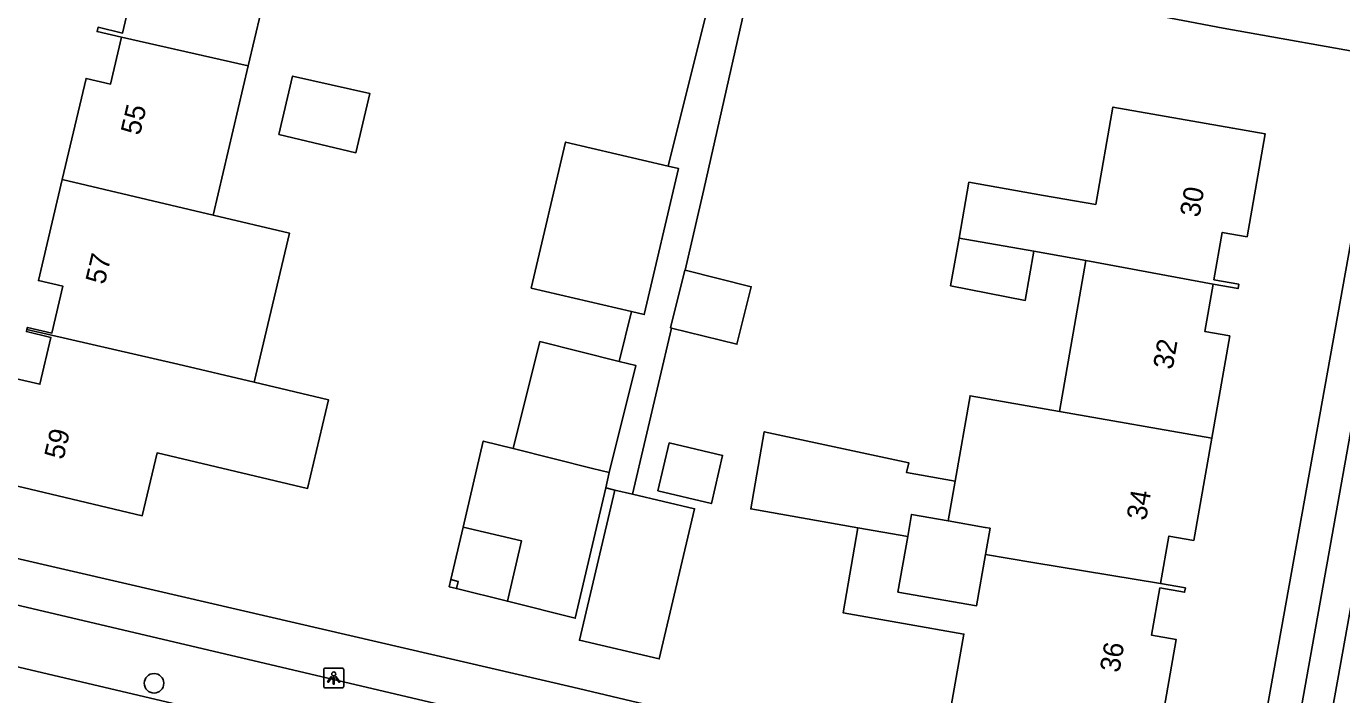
# Model space of a CAD drawing. Extents: x 163686 to 164493, y 382719 to 383870.
# Drawn here: x 163838.9 to 163904.7, y 383427.9 to 383461.3 of the extents above; entities that cross this region are included whole.
import ezdxf

# ---------------------------------------------------------------- set-up
doc = ezdxf.new("R2010")
doc.units = 0
for name, color, linetype in [('IMGEO_Boom', 7, 'Continuous'), ('IMGEO_Groenvoorziening', 7, 'Continuous'), ('IMGEO_Lichtpunt', 7, 'Continuous'), ('IMGEO_Muur', 7, 'Continuous'), ('IMGEO_Pand', 7, 'Continuous'), ('IMGEO_Pand_nummerreeks', 7, 'Continuous'), ('IMGEO_Pand_overbouw', 7, 'Continuous'), ('IMGEO_Rijbaan_lokaal_open', 7, 'Continuous'), ('IMGEO_Voetpad_open', 7, 'Continuous')]:
    doc.layers.add(name, color=color, linetype=linetype)

msp = doc.modelspace()

# ---------------------------------------------------------------- linework, layer by layer
at = {"layer": 'IMGEO_Boom'}
msp.add_circle((163845.296, 383428.434), 0.489, dxfattribs=at)
at = {"layer": 'IMGEO_Groenvoorziening'}
msp.add_lwpolyline([(163861.569, 383423.819), (163837.373, 383429.512)], dxfattribs=at)
at = {"layer": 'IMGEO_Lichtpunt'}
for p, q in [((163853.789, 383429.101), (163853.789, 383428.294)), ((163853.789, 383429.101), (163853.789, 383428.294)), ((163854.691, 383429.196), (163853.883, 383429.196)), ((163854.691, 383429.196), (163853.883, 383429.196)), ((163854.785, 383428.294), (163854.785, 383429.101)), ((163854.785, 383428.294), (163854.785, 383429.101)), ((163853.883, 383428.2), (163854.691, 383428.2)), ((163853.883, 383428.2), (163854.691, 383428.2))]:
    msp.add_line(p, q, dxfattribs=at)
for points in [[(163854.163, 383428.765), (163854.202, 383428.737), (163854.014, 383428.475), (163853.976, 383428.502), (163854.163, 383428.765)], [(163854.265, 383428.717), (163854.312, 383428.717), (163854.312, 383428.395), (163854.265, 383428.395), (163854.265, 383428.717)], [(163854.375, 383428.737), (163854.413, 383428.764), (163854.6, 383428.502), (163854.561, 383428.474), (163854.375, 383428.737)]]:
    msp.add_lwpolyline(points, dxfattribs=at)
msp.add_circle((163854.288, 383428.899), 0.0994, dxfattribs=at)
for centre, start, end in [((163853.883, 383429.101), 90, 180), ((163853.883, 383429.101), 90, 180), ((163854.691, 383429.101), 0, 90), ((163854.691, 383429.101), 0, 90), ((163853.883, 383428.294), 180, 270), ((163853.883, 383428.294), 180, 270), ((163854.691, 383428.294), 270, 0), ((163854.691, 383428.294), 270, 360)]:
    msp.add_arc(centre, 0.0946, start, end, dxfattribs=at)
at = {"layer": 'IMGEO_Muur'}
for points in [[(163837.936, 383434.797), (163843.936, 383433.408)], [(163843.936, 383433.408), (163866.249, 383428.241)]]:
    msp.add_lwpolyline(points, dxfattribs=at)
at = {"layer": 'IMGEO_Pand'}
for points in [[(163843.673, 383460.79), (163842.444, 383461.07), (163842.494, 383461.284), (163843.721, 383460.996), (163844.274, 383463.342), (163843.047, 383463.63), (163844.242, 383468.706), (163844.827, 383468.569), (163851.79, 383466.938), (163850.633, 383462.021), (163850.004, 383459.348)], [(163840.698, 383453.655), (163841.892, 383458.724), (163843.118, 383458.436), (163843.673, 383460.79)], [(163850.004, 383459.348), (163843.673, 383460.79)], [(163850.004, 383459.348), (163848.246, 383451.878)], [(163851.535, 383455.906), (163852.225, 383458.842), (163856.096, 383457.96), (163855.4, 383454.996), (163851.535, 383455.906)], [(163885.579, 383450.722), (163886.071, 383453.525), (163889.815, 383452.867), (163892.422, 383452.409), (163893.278, 383457.284), (163893.95, 383457.166), (163899.278, 383456.23), (163900.903, 383455.945), (163899.998, 383450.792), (163898.757, 383451.01), (163898.34, 383448.636), (163899.581, 383448.418), (163899.543, 383448.201), (163898.302, 383448.419)], [(163871.016, 383454.334), (163865.887, 383455.534), (163864.176, 383448.22), (163869.197, 383447.045)], [(163869.197, 383447.045), (163869.825, 383446.898), (163871.536, 383454.212), (163871.016, 383454.334)], [(163838.93, 383446.148), (163838.955, 383446.255), (163840.182, 383445.967), (163840.735, 383448.313), (163839.506, 383448.601), (163840.698, 383453.655)], [(163848.246, 383451.878), (163840.698, 383453.655)], [(163848.246, 383451.878), (163852.066, 383450.979), (163850.307, 383443.507)], [(163889.322, 383450.064), (163888.89, 383447.604), (163885.161, 383448.343), (163885.579, 383450.722)], [(163885.579, 383450.722), (163889.322, 383450.064)], [(163891.93, 383449.606), (163889.322, 383450.064)], [(163890.603, 383442.047), (163891.93, 383449.606)], [(163898.302, 383448.419), (163891.93, 383449.606)], [(163871.189, 383446.223), (163871.142, 383446.235), (163871.862, 383449.12), (163871.868, 383449.118)], [(163871.189, 383446.223), (163874.461, 383445.407), (163875.181, 383448.291), (163871.868, 383449.118)], [(163898.302, 383448.419), (163897.886, 383446.046), (163899.126, 383445.828), (163898.227, 383440.708)], [(163850.307, 383443.507), (163854.021, 383442.632), (163852.977, 383438.193), (163845.445, 383439.968), (163844.705, 383436.825), (163838.738, 383438.231), (163837.153, 383438.604), (163837.497, 383440.064), (163837.063, 383440.536), (163837.497, 383442.376), (163838.095, 383442.605), (163838.352, 383443.695), (163839.579, 383443.407), (163840.132, 383445.753), (163838.904, 383446.041), (163838.93, 383446.148)], [(163850.307, 383443.507), (163846.489, 383444.407), (163838.93, 383446.148)], [(163868.575, 383444.552), (163864.608, 383445.542), (163863.271, 383440.185)], [(163868.077, 383438.986), (163869.414, 383444.342), (163868.575, 383444.552)], [(163885.38, 383438.557), (163886.131, 383442.832), (163890.603, 383442.047)], [(163890.603, 383442.047), (163898.227, 383440.708)], [(163880.522, 383436.219), (163875.153, 383437.162), (163875.832, 383441.026), (163883.065, 383439.476), (163882.959, 383438.982), (163885.38, 383438.557)], [(163863.271, 383440.185), (163861.77, 383440.56), (163860.763, 383436.246), (163863.685, 383435.564), (163862.979, 383432.538), (163866.374, 383431.691), (163867.897, 383438.216)], [(163870.51, 383438.062), (163873.186, 383437.435), (163873.75, 383439.841), (163871.074, 383440.469), (163870.51, 383438.062)], [(163898.227, 383440.708), (163897.327, 383435.584), (163896.087, 383435.802), (163895.67, 383433.428)], [(163863.271, 383440.185), (163867.238, 383439.195), (163868.077, 383438.986)], [(163867.897, 383438.216), (163868.077, 383438.986)], [(163885.38, 383438.557), (163885.031, 383436.568)], [(163869.238, 383437.902), (163872.342, 383437.174), (163870.579, 383429.65), (163866.583, 383430.587), (163868.347, 383438.111)], [(163868.347, 383438.111), (163869.238, 383437.902)], [(163885.031, 383436.568), (163883.206, 383436.889), (163883.012, 383435.782)], [(163886.906, 383434.88), (163887.138, 383436.198), (163886.894, 383436.241), (163885.031, 383436.568)], [(163895.67, 383433.428), (163896.91, 383433.21), (163896.872, 383432.993), (163895.632, 383433.211), (163895.215, 383430.838), (163896.455, 383430.62), (163895.551, 383425.468), (163887.93, 383426.822), (163885.191, 383427.309), (163885.822, 383430.9), (163879.775, 383431.962), (163880.522, 383436.219)], [(163883.012, 383435.782), (163880.522, 383436.219)], [(163883.012, 383435.782), (163882.523, 383433.003), (163886.455, 383432.313), (163886.906, 383434.88)], [(163895.67, 383433.428), (163889.276, 383434.487), (163886.906, 383434.88)], [(163860.51, 383433.536), (163860.151, 383433.625), (163860.067, 383433.265), (163860.426, 383433.175), (163860.51, 383433.536)]]:
    msp.add_lwpolyline(points, dxfattribs=at)
at = {"layer": 'IMGEO_Pand_overbouw'}
msp.add_lwpolyline([(163860.426, 383433.175), (163862.979, 383432.538), (163863.685, 383435.564), (163860.763, 383436.246), (163860.151, 383433.625), (163860.51, 383433.536)], close=True, dxfattribs=at)
at = {"layer": 'IMGEO_Rijbaan_lokaal_open'}
msp.add_lwpolyline([(163903.693, 383423.896), (163908.69, 383451.789)], dxfattribs=at)
at = {"layer": 'IMGEO_Voetpad_open'}
for points in [[(163840.13, 383473.739), (163845.744, 383472.463), (163852.703, 383470.821), (163852.704, 383470.825), (163871.126, 383466.513), (163873.922, 383465.981), (163871.016, 383454.334)], [(163871.868, 383449.118), (163872.815, 383453.155), (163875.623, 383465.657), (163898.807, 383461.246), (163906.853, 383459.8)], [(163899.759, 383420.325), (163906.853, 383459.8)], [(163902.632, 383426.799), (163906.691, 383449.49)], [(163869.197, 383447.045), (163868.575, 383444.552)], [(163869.238, 383437.902), (163871.189, 383446.223)], [(163867.897, 383438.216), (163868.347, 383438.111)], [(163831.477, 383436.455), (163837.936, 383434.797), (163843.936, 383433.408), (163866.249, 383428.241), (163868.851, 383427.627), (163899.759, 383420.325)], [(163838.037, 383432.437), (163862.222, 383426.748)]]:
    msp.add_lwpolyline(points, dxfattribs=at)

# ---------------------------------------------------------------- texts
at = {"layer": 'IMGEO_Pand_nummerreeks'}
for s, rotation, p in [('55', 76.74197, (163844.582, 383455.833)), ('30', 80.03896, (163897.604, 383451.731)), ('57', 76.73051, (163842.82, 383448.362)), ('32', 80.03957, (163896.265, 383444.107)), ('59', 76.7477, (163840.756, 383439.593)), ('34', 80.0422, (163894.938, 383436.551)), ('36', 80.04793, (163893.599, 383428.93))]:
    msp.add_text(s, height=1, rotation=rotation, dxfattribs=at).set_placement(p)

doc.saveas('drawing.dxf')
